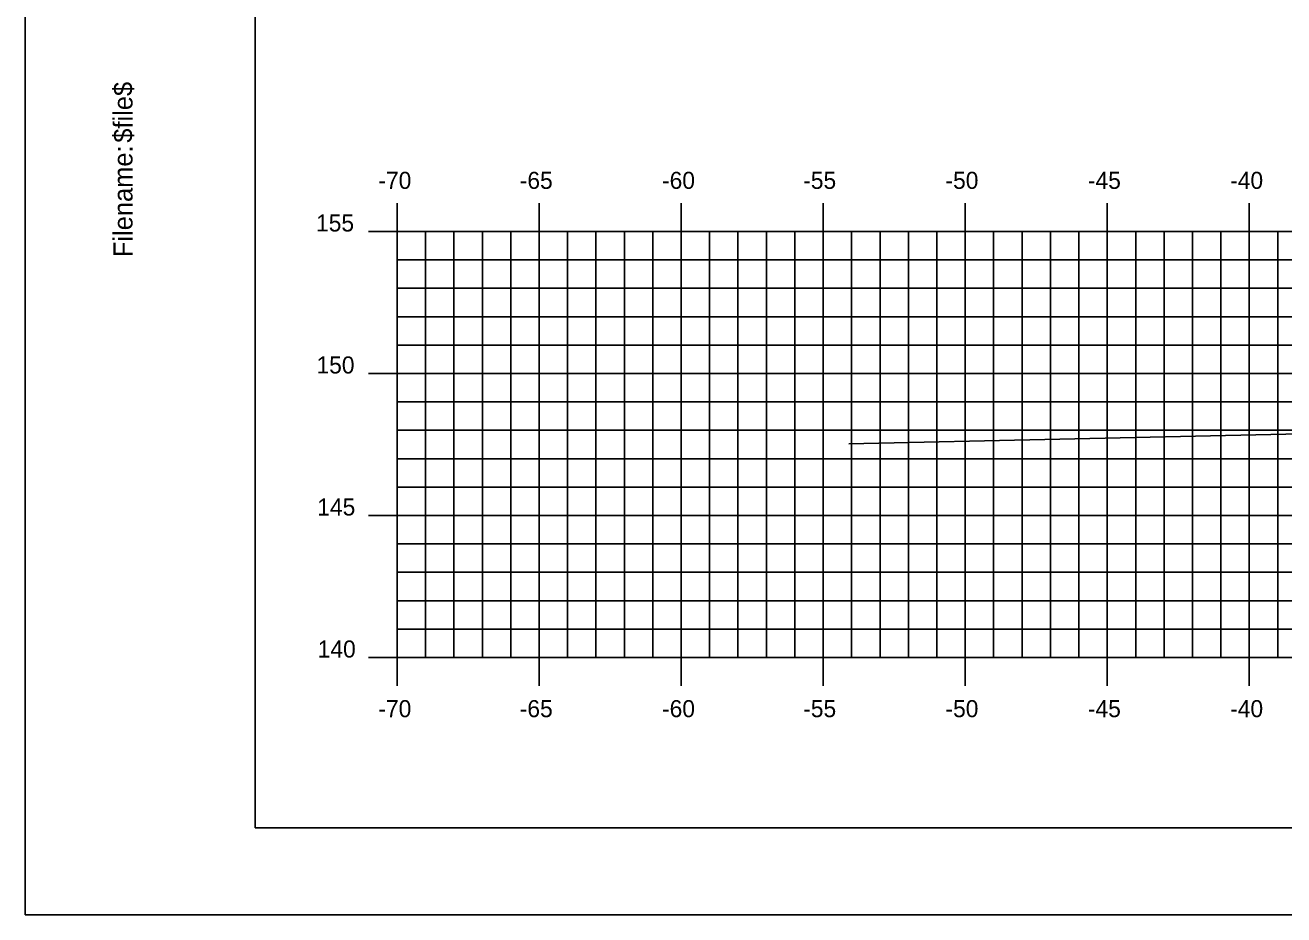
# Model space of a CAD drawing. Extents: x 1147190 to 1147360, y 608981 to 609091.
# Drawn here: x 1147189.85 to 1147234.16, y 608981.28 to 609012.6 of the extents above; entities that cross this region are included whole.
import ezdxf

# ---------------------------------------------------------------- set-up
doc = ezdxf.new("R2010")
doc.units = 0
for name, color, linetype in [('BORDER', 7, 'Continuous'), ('H_V ANNOTATION', 7, 'Continuous'), ('MAJOR', 7, 'Continuous'), ('MINOR', 7, 'Continuous'), ('PLOT BOUNDARY', 7, 'Continuous'), ('S_Roadway_Centerline', 7, 'Continuous')]:
    doc.layers.add(name, color=color, linetype=linetype)

msp = doc.modelspace()

# ---------------------------------------------------------------- linework, layer by layer
at = {"layer": 'BORDER'}
msp.add_lwpolyline([(1147197.941, 608984.335), (1147357.941, 608984.335), (1147357.941, 609089.335), (1147197.941, 609089.335)], close=True, dxfattribs=at)
at = {"layer": 'MAJOR'}
for p, q in [((1147202.941, 609006.337), (1147202.941, 609005.335)), ((1147207.941, 609006.337), (1147207.941, 609005.335)), ((1147212.941, 609006.337), (1147212.941, 609005.335)), ((1147217.941, 609006.337), (1147217.941, 609005.335)), ((1147222.941, 609006.337), (1147222.941, 609005.335)), ((1147227.941, 609006.337), (1147227.941, 609005.335)), ((1147232.941, 609006.337), (1147232.941, 609005.335)), ((1147201.939, 609005.335), (1147202.941, 609005.335)), ((1147202.941, 609005.335), (1147342.941, 609005.335)), ((1147202.941, 608990.335), (1147202.941, 609005.335)), ((1147202.941, 608990.335), (1147202.941, 609005.335)), ((1147202.941, 609005.335), (1147342.941, 609005.335)), ((1147207.941, 608990.335), (1147207.941, 609005.335)), ((1147212.941, 608990.335), (1147212.941, 609005.335)), ((1147217.941, 608990.335), (1147217.941, 609005.335)), ((1147222.941, 608990.335), (1147222.941, 609005.335)), ((1147227.941, 608990.335), (1147227.941, 609005.335)), ((1147232.941, 608990.335), (1147232.941, 609005.335)), ((1147201.939, 609000.335), (1147202.941, 609000.335)), ((1147202.941, 609000.335), (1147342.941, 609000.335)), ((1147201.939, 608995.335), (1147202.941, 608995.335)), ((1147202.941, 608995.335), (1147342.941, 608995.335)), ((1147201.939, 608990.335), (1147202.941, 608990.335)), ((1147202.941, 608990.335), (1147342.941, 608990.335)), ((1147202.941, 608990.335), (1147342.941, 608990.335)), ((1147202.941, 608989.333), (1147202.941, 608990.335)), ((1147207.941, 608989.333), (1147207.941, 608990.335)), ((1147212.941, 608989.333), (1147212.941, 608990.335)), ((1147217.941, 608989.333), (1147217.941, 608990.335)), ((1147222.941, 608989.333), (1147222.941, 608990.335)), ((1147227.941, 608989.333), (1147227.941, 608990.335)), ((1147232.941, 608989.333), (1147232.941, 608990.335))]:
    msp.add_line(p, q, dxfattribs=at)
at = {"layer": 'MINOR'}
for p, q in [((1147203.941, 608990.335), (1147203.941, 609005.335)), ((1147204.941, 608990.335), (1147204.941, 609005.335)), ((1147205.941, 608990.335), (1147205.941, 609005.335)), ((1147206.941, 608990.335), (1147206.941, 609005.335)), ((1147208.941, 608990.335), (1147208.941, 609005.335)), ((1147209.941, 608990.335), (1147209.941, 609005.335)), ((1147210.941, 608990.335), (1147210.941, 609005.335)), ((1147211.941, 608990.335), (1147211.941, 609005.335)), ((1147213.941, 608990.335), (1147213.941, 609005.335)), ((1147214.941, 608990.335), (1147214.941, 609005.335)), ((1147215.941, 608990.335), (1147215.941, 609005.335)), ((1147216.941, 608990.335), (1147216.941, 609005.335)), ((1147218.941, 608990.335), (1147218.941, 609005.335)), ((1147219.941, 608990.335), (1147219.941, 609005.335)), ((1147220.941, 608990.335), (1147220.941, 609005.335)), ((1147221.941, 608990.335), (1147221.941, 609005.335)), ((1147223.941, 608990.335), (1147223.941, 609005.335)), ((1147224.941, 608990.335), (1147224.941, 609005.335)), ((1147225.941, 608990.335), (1147225.941, 609005.335)), ((1147226.941, 608990.335), (1147226.941, 609005.335)), ((1147228.941, 608990.335), (1147228.941, 609005.335)), ((1147229.941, 608990.335), (1147229.941, 609005.335)), ((1147230.941, 608990.335), (1147230.941, 609005.335)), ((1147231.941, 608990.335), (1147231.941, 609005.335)), ((1147233.941, 608990.335), (1147233.941, 609005.335)), ((1147202.941, 609004.335), (1147342.941, 609004.335)), ((1147202.941, 609004.335), (1147203.943, 609004.335)), ((1147202.941, 609003.335), (1147342.941, 609003.335)), ((1147202.941, 609003.335), (1147203.943, 609003.335)), ((1147202.941, 609002.335), (1147342.941, 609002.335)), ((1147202.941, 609002.335), (1147203.943, 609002.335)), ((1147202.941, 609001.335), (1147342.941, 609001.335)), ((1147202.941, 609001.335), (1147203.943, 609001.335)), ((1147202.941, 608999.335), (1147342.941, 608999.335)), ((1147202.941, 608999.335), (1147203.943, 608999.335)), ((1147202.941, 608998.335), (1147342.941, 608998.335)), ((1147202.941, 608998.335), (1147203.943, 608998.335)), ((1147202.941, 608997.335), (1147342.941, 608997.335)), ((1147202.941, 608997.335), (1147203.943, 608997.335)), ((1147202.941, 608996.335), (1147342.941, 608996.335)), ((1147202.941, 608996.335), (1147203.943, 608996.335)), ((1147202.941, 608994.335), (1147342.941, 608994.335)), ((1147202.941, 608994.335), (1147203.943, 608994.335)), ((1147202.941, 608993.335), (1147342.941, 608993.335)), ((1147202.941, 608993.335), (1147203.943, 608993.335)), ((1147202.941, 608992.335), (1147342.941, 608992.335)), ((1147202.941, 608992.335), (1147203.943, 608992.335)), ((1147202.941, 608991.335), (1147342.941, 608991.335)), ((1147202.941, 608991.335), (1147203.943, 608991.335))]:
    msp.add_line(p, q, dxfattribs=at)
at = {"layer": 'PLOT BOUNDARY'}
msp.add_lwpolyline([(1147189.848, 608981.276), (1147359.848, 608981.276), (1147359.848, 609091.276), (1147189.848, 609091.276)], close=True, dxfattribs=at)
at = {"layer": 'S_Roadway_Centerline'}
msp.add_lwpolyline([(1147218.846, 608997.864), (1147241.122, 608998.353), (1147247.885, 608998.514), (1147248.984, 608998.516), (1147254.873, 608998.314), (1147257.094, 608998.713), (1147257.502, 608998.83), (1147259.688, 608998.949), (1147260.064, 608998.953), (1147270.445, 608999.103), (1147271.787, 608999.116), (1147281.744, 608998.963), (1147282.951, 608998.947), (1147286.36, 608998.968), (1147286.809, 608998.965), (1147292.313, 608998.283), (1147293.044, 608998.205), (1147296.983, 608997.246), (1147297.425, 608997.25), (1147298.007, 608997.262), (1147306.226, 608998.28), (1147306.772, 608998.268), (1147312.322, 608998.262)], dxfattribs=at)

# ---------------------------------------------------------------- texts
at = {"layer": 'BORDER'}
for s, p in [('$file$', (1147193.626, 609008.461)), ('Filename:', (1147193.626, 609004.433))]:
    msp.add_text(s, height=0.6696, rotation=90, dxfattribs=at).set_placement(p)
at = {"layer": 'H_V ANNOTATION'}
for s, p in [('-70', (1147202.282, 609006.835)), ('-65', (1147207.259, 609006.835)), ('-60', (1147212.267, 609006.835)), ('-55', (1147217.237, 609006.835)), ('-50', (1147222.245, 609006.835)), ('-45', (1147227.259, 609006.835)), ('-40', (1147232.267, 609006.835)), ('155', (1147200.087, 609005.335)), ('150', (1147200.103, 609000.335)), ('145', (1147200.13, 608995.335)), ('140', (1147200.146, 608990.335)), ('-70', (1147202.282, 608988.235)), ('-65', (1147207.259, 608988.235)), ('-60', (1147212.267, 608988.235)), ('-55', (1147217.237, 608988.235)), ('-50', (1147222.245, 608988.235)), ('-45', (1147227.259, 608988.235)), ('-40', (1147232.267, 608988.235))]:
    msp.add_text(s, height=0.6, dxfattribs=at).set_placement(p)
at = {"layer": 'MAJOR'}
msp.add_text('-', height=0.006, dxfattribs=at).set_placement((1147202.936, 608990.335))

doc.saveas('drawing.dxf')
